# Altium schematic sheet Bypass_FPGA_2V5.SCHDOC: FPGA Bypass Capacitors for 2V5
size A4; Organization: Altium Limited.; Address1: Level 3, 12a Rodborough Rd; Address2: Frenchs Forest 2086; Address3: NSW; Address4: AUSTRALIA; DocumentNumber: 6; SheetNumber: 6; SheetTotal: 23
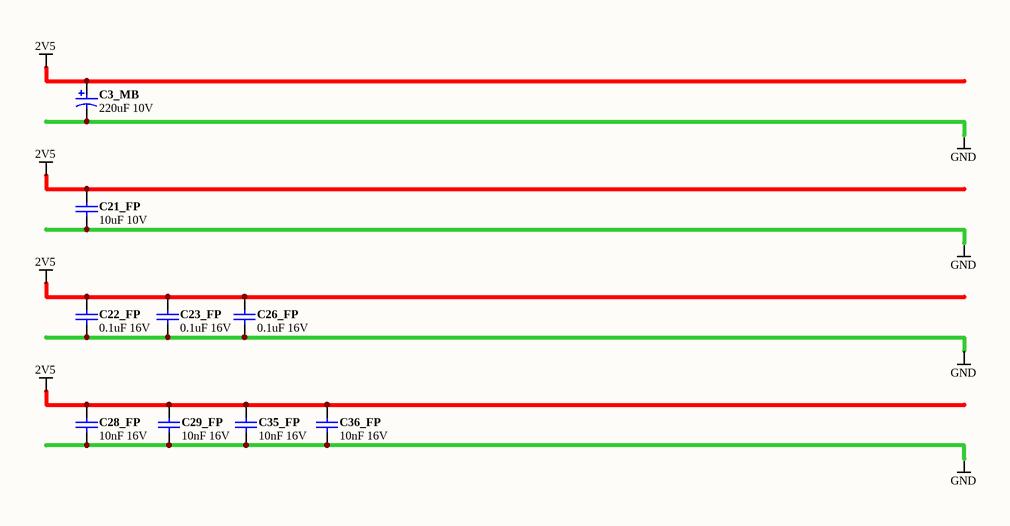
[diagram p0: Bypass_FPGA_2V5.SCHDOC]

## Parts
C3_MB  220uF 10V  [CAPC7343-STAR]
C21_FP  10uF 10V  [CAPC2012-STAR]
C22_FP  0.1uF 16V  [CAPC1005-STAR]
C23_FP  0.1uF 16V  [CAPC1005-STAR]
C26_FP  0.1uF 16V  [CAPC1005-STAR]
C28_FP  10nF 16V  [CAPC1005-STAR]
C29_FP  10nF 16V  [CAPC1005-STAR]
C35_FP  10nF 16V  [CAPC1005-STAR]
C36_FP  10nF 16V  [CAPC1005-STAR]

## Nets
2V5: C3_MB.1 C21_FP.1 C22_FP.1 C23_FP.1 C26_FP.1 C28_FP.1 C29_FP.1 C35_FP.1 C36_FP.1
GND: C3_MB.2 C21_FP.2 C22_FP.2 C23_FP.2 C26_FP.2 C28_FP.2 C29_FP.2 C35_FP.2 C36_FP.2

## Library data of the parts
C3_MB = D-101-0088: Capacitor, Tantalum, 220uF 10% 10V MCCT-D (7343-31); Polarity: Polarized
C21_FP = D-101-0087: Capacitor, Ceramic, 10uF 10% 10V 0805 (2012) X5R; Polarity: Non-Polarized
C22_FP C23_FP C26_FP = D-101-0080: Capacitor, Ceramic, 0.1uF 10% 16V 0402 (1005) X7R; Polarity: Non-Polarized
C28_FP C29_FP C35_FP C36_FP = D-101-0077: Capacitor, Ceramic, 10nF 10% 16V 0402 (1005) X7R; Polarity: Non-Polarized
